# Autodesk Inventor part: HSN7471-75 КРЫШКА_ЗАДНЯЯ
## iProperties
Created: 2011-02
Part Number: HSN7471-75 КРЫШКА_ЗАДНЯЯ
Document SubType Name: Modeling
Designer: Чернышев Юрий
Mass: 3099.53 g
Surface Area: 2240.83 cm^2
Volume: 3099.53 cm^3
Density: 1 g/cm^3
Author: Чернышев Юрий
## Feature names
1. ExtrusionBlind1
2. RevolutionAngle1
3. ExtrusionBlind2
4. AM_HOLE_0301DE_1 [Hole]
5. PolarPattern1 [Circular Pattern]
6. Fillet1
7. Hole1
8. Hole2
9. Hole3
10. Hole4
11. Fillet2
12. Fillet3
13. Fillet4
14. Hole5
